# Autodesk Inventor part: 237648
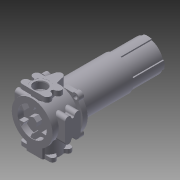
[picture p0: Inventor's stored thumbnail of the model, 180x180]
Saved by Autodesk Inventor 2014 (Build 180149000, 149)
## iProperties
Shininess: 20.0
Length Units: 11272
Angle Units: 11279
Time Units: 11290
Mass Units: 11286
Length Display Precision: 3
Angle Display Precision: 2
Company: Autodesk, Inc.
Created: 2002-06
Part Number: 237648
Material: Aluminum-6061
Description: FILTER
Document SubType Name: Modeling
Designer: Autodesk, Inc.
Density: 2.71 g/cm^3
Mass: 11418.8 g
Surface Area: 2406.98 cm^2
Volume: 4213.59 cm^3
Appearance: Metal-AL-6061(Flat)
Density: 0.0
Volumn: 0.0
Area: 0.0
PropertySet Name: Model Information
Control State: 0
Master: False
Checked Out: False
Last Check In By: JT
Last Check In Date: 2003-06-20
Title: FILTER
Author: Autodesk, Inc.
Comments: POSITIONAL ACCURACY OF ALL PORTS IS QUESTIONABLE.  CHECK FOR YOUR APPLICATION.
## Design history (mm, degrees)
sketch "Sketch1"
  geometry: C1 r 54.769 at (0, 0); 1 further point
  constraints: 1 centre point, 1 coincident
  dimensions: "d3" = 109.5375 diameter of C1
extrude "Extrusion2" new body sketch "Sketch1" distance "d4" = 273.685; taper "d5" = 0 deg
sketch "Sketch2"
  geometry: L1 (-49.187, 12.7)-(-60.596, 12.7); L2 (-12.7, 60.596)-(-12.7, 49.187); L3 (12.7, 60.596)-(12.7, 49.187); L4 (60.596, 12.7)-(49.187, 12.7); L5 (49.187, -12.7)-(60.596, -12.7); L6 (12.7, -49.187)-(12.7, -60.596); L7 (-12.7, -49.187)-(-12.7, -60.596); L8 (-60.596, -12.7)-(-49.187, -12.7); C1 r 54.769 at (0, 0) reference; A1 r 50.8 centre (0, 0) between (-12.7, 49.187) and (-49.187, 12.7); A2 r 50.8 centre (0, 0) between (49.187, 12.7) and (12.7, 49.187); A3 r 50.8 centre (0, 0) between (-49.187, -12.7) and (-12.7, -49.187); A4 r 50.8 centre (0, 0) between (12.7, -49.187) and (49.187, -12.7); 1 further point
  constraints: 16 end point, 8 parallel, 8 point on circle, 4 centre point, 4 collinear, 4 perpendicular, 3 concentric, 2 vertical, 1 coincident, 10 other
  dimensions: "d6" = 50.8 radius of A2; "d7" = 12.7 distance from line of point (0, 0) L3; "d8" = 25.4 distance between parallel lines of L2 L3; "d9" = 12.7 distance from line of point (0, 0) L4; "d10" = 25.4 distance between parallel lines of L5 L4
extrude "Extrusion3" cut sketch "Sketch2" distance "d11" = 101.6; taper "d12" = 0 deg
sketch "Sketch3"
  geometry: L1 (-43.017, 60.96)-(43.017, 60.96); L2 (43.017, -60.96)-(-43.017, -60.96); C1 r 61.912 at (0, 0); C2 r 6.731 at (-52.388, 52.388); C3 r 6.731 at (52.388, 52.388); C4 r 6.731 at (52.388, -52.388); C5 r 6.731 at (-52.388, -52.388); C6 r 54.769 at (0, 0) reference; A1 r 12.7 centre (-52.388, -52.388) between (-62.48, -44.678) and (-43.017, -60.96); A2 r 12.7 centre (52.388, -52.388) between (43.017, -60.96) and (62.348, -44.508); A3 r 12.7 centre (52.388, 52.388) between (62.348, 44.508) and (43.017, 60.96); A4 r 12.7 centre (-52.388, 52.388) between (-43.017, 60.96) and (-62.48, 44.678); A5 r 76.604 centre (-0.254, 0) between (-62.48, 44.678) and (-62.48, -44.678); A6 r 76.604 centre (0, 0) between (62.348, -44.508) and (62.348, 44.508)
  constraints: 12 point on circle, 11 centre point, 7 equal radius, 6 coincident, 4 end point, 4 vertical alignment, 2 horizontal alignment, 2 parallel, 1 horizontal
  dimensions: "d13" = 13.462 diameter of C2; "d18" = 25.4 diameter of A4; "d19" = 60.96 distance from line of C1.centre L1; "d23" = 0.254 distance of A5.centre A6.centre; "d83" = 123.825 diameter of C1; "d84" = 52.3875 horizontal distance of A6.centre C2.centre; "d85" = 104.775 distance of C3.centre C2.centre; "d87" = 52.3875 vertical distance of C2.centre A5.centre
extrude "Extrusion4" join sketch "Sketch3" distance "d24" = 15.875; taper "d25" = 0 deg
sketch "Sketch4"
  geometry: L1 (-44.678, 15.875)-(44.678, 15.875) reference; L2 (61.912, 15.875)-(61.912, 88.9); L3 (61.912, 88.9)-(63.5, 88.9); L4 (63.5, 88.9)-(63.5, 98.425); L5 (63.5, 98.425)-(66.675, 98.425); L6 (66.675, 98.425)-(66.675, 104.775); L7 (66.675, 104.775)-(47.625, 104.775); L8 (0, 0)-(0, 153.89); L9 (61.912, 15.875)-(0, 15.875); L10 (0, 85.725)-(0, 15.875); L11 (47.625, 104.775)-(47.625, 85.725); L12 (47.625, 85.725)-(0, 85.725)
  constraints: 22 end point, 5 parallel, 4 perpendicular, 2 point on line, 1 collinear, 1 midpoint
  dimensions: "d26" = 133.35 diameter of L6 L8; "d27" = 6.35 distance of L5.end L6.end; "d28" = 9.525 distance of L3.end L4.end; "d29" = 127 diameter of L4 L8; "d30" = 123.825 diameter of L2 L8; "d31" = 88.9 distance between parallel lines of L1 L7; "d32" = 95.25 diameter of L11 L8; "d33" = 19.05 distance of L7.end L11.end
revolve "Revolution1" sketch "Sketch4" stored, may be unused: angle "d34" = 90 deg
sketch "Sketch5"
  geometry: L1 (-7.84, 46.975)-(-1.439, 33.248); L2 (1.439, 33.248)-(7.84, 46.975); L3 (7.84, 46.975)-(-7.84, 46.975); L4 (-44.602, 16.698)-(-29.513, 15.378); L5 (-28.074, 17.87)-(-36.762, 30.277); L6 (-36.762, -30.277)-(-28.074, -17.87); L7 (-29.513, -15.378)-(-44.602, -16.698); L8 (7.84, -46.975)-(1.439, -33.248); L9 (-1.439, -33.248)-(-7.84, -46.975); L10 (44.602, -16.698)-(29.513, -15.378); L11 (28.074, -17.87)-(36.762, -30.277); L12 (36.762, 30.277)-(28.074, 17.87); L13 (29.513, 15.378)-(44.602, 16.698); L14 (-11.005, 9.509)-(2.733, 14.285); L15 (2.733, 14.285)-(13.737, 4.776); L16 (13.737, 4.776)-(11.005, -9.509); L17 (11.005, -9.509)-(-2.733, -14.285); L18 (-2.733, -14.285)-(-13.737, -4.776); L19 (-13.737, -4.776)-(-11.005, 9.509); A1 r 47.625 centre (0, 0) between (-7.84, 46.975) and (7.84, 46.975) reference; A2 r 1.587 centre (-29.375, 16.959) between (-29.513, 15.378) and (-28.074, 17.87); A3 r 1.587 centre (-29.375, -16.959) between (-28.074, -17.87) and (-29.513, -15.378); A4 r 1.588 centre (0, -33.919) between (1.439, -33.248) and (-1.439, -33.248); A5 r 1.587 centre (29.375, -16.959) between (29.513, -15.378) and (28.074, -17.87); A6 r 1.588 centre (29.375, 16.959) between (28.074, 17.87) and (29.513, 15.378); A7 r 1.588 centre (0, 33.919) between (-1.439, 33.248) and (1.439, 33.248); A8 r 47.625 centre (0, 0) between (-7.84, -46.975) and (7.84, -46.975); A9 r 47.625 centre (0, 0) between (36.762, -30.277) and (44.602, -16.698); A10 r 47.625 centre (0, 0) between (44.602, 16.698) and (36.762, 30.277); A11 r 47.625 centre (0, 0) between (7.84, 46.975) and (-7.84, 46.975); A12 r 47.625 centre (0, 0) between (-36.762, 30.277) and (-44.602, 16.698); A13 r 47.625 centre (0, 0) between (-44.602, -16.698) and (-36.762, -30.277); 8 further points
  constraints: 38 end point, 26 point on circle, 12 centre point, 12 point on line, 12 tangent, 4 equal radius, 2 coincident, 1 horizontal, 1 vertical alignment, 44 other
  dimensions: "d35" = 50 deg angle of L1 L2; "d36" = 30.1625 distance of A1.centre point (0, 30.162); "d39" = 360 deg dimension on A1.centre L1.start (derived); "d41" = 1.5875 radius of A2; "d42" = 1.5875 radius of A3
extrude "Extrusion5" join sketch "Sketch5" distance "d43" = 17.4625; taper "d44" = 0 deg
sketch "Sketch6"
  geometry: L1 (-29.369, 79.756)-(29.369, 79.756); L2 (29.369, 28.956)-(-29.369, 28.956); L3 (-29.369, 69.437)-(29.369, 39.275); L4 (0, 54.356)-(29.369, 69.437); A1 r 10.319 centre (29.369, 69.437) between (31.121, 59.268) and (29.369, 79.756); A2 r 4.985 centre (31.967, 54.356) between (31.121, 59.268) and (31.121, 49.444); A3 r 10.319 centre (29.369, 39.275) between (29.369, 28.956) and (31.121, 49.444); A4 r 10.319 centre (-29.369, 39.275) between (-31.121, 49.444) and (-29.369, 28.956); A5 r 4.985 centre (-31.967, 54.356) between (-31.121, 49.444) and (-31.121, 59.268); A6 r 10.319 centre (-29.369, 69.437) between (-29.369, 79.756) and (-31.121, 59.268); 1 further point
  constraints: 12 point on circle, 8 end point, 7 tangent, 6 centre point, 3 equal radius, 3 vertical alignment, 2 horizontal alignment, 1 horizontal, 1 midpoint, 1 parallel
  dimensions: "d45" = 30.1625 distance of A4.centre L3.start; "d46" = 58.7375 distance of L4.end L3.start; "d47" = 10.31875 radius of A6; "d48" = 54.356 distance of point (0, 0) L4.start
extrude "Extrusion6" join sketch "Sketch6" stored distance "d49" = 165.1; taper "d50" = 0 deg
workplane "Work Plane1"
sketch "Sketch8"
  geometry: L1 (35.076, 102.787)-(34.925, 102.787); L2 (34.925, 102.787)-(-34.925, 102.787); L3 (19.05, 43.263)-(12.331, 16.01); L4 (-12.331, 16.01)-(-19.05, 43.263); L5 (-34.925, 90.881)-(34.925, 55.169); L6 (0, 73.025)-(34.925, 90.881); L7 (-34.925, 43.263)-(-19.05, 43.263); L8 (19.05, 43.263)-(34.925, 43.263); A1 r 11.906 centre (-34.925, 90.881) between (-34.925, 102.787) and (-35.869, 79.012); A2 r 6.006 centre (-36.345, 73.025) between (-35.869, 67.038) and (-35.869, 79.012); A3 r 11.906 centre (-34.925, 55.169) between (-35.869, 67.038) and (-34.925, 43.263); A4 r 11.906 centre (34.925, 55.169) between (34.925, 43.263) and (33.981, 67.038); A5 r 6.006 centre (33.505, 73.025) between (33.981, 79.012) and (33.981, 67.038); A6 r 11.906 centre (34.925, 90.881) between (33.981, 79.012) and (34.925, 102.787); A7 r 12.7 centre (0, 19.05) between (-12.331, 16.01) and (12.331, 16.01); 1 further point
  constraints: 16 end point, 14 point on circle, 11 tangent, 7 centre point, 4 vertical alignment, 3 equal radius, 2 horizontal alignment, 2 parallel, 1 collinear, 1 horizontal, 1 midpoint
  dimensions: "d56" = 35.7124 distance of L5.end L6.end; "d57" = 69.85 distance of L5.start L6.end; "d58" = 19.05 horizontal distance of L3.start A7.centre; "d59" = 19.05 horizontal distance of L4.end A7.centre; "d60" = 12.7 radius of A7; "d61" = 73.025 distance of L6.start point (0, 0); "d62" = 11.90625 radius of A6; "d63" = 19.05 distance of point (0, 0) A7.centre
extrude "Extrusion8" join sketch "Sketch8" distance "d64" = 15.875; taper "d65" = 0 deg
sketch "Sketch9"
  geometry: L1 (-19.05, -43.263)-(-24.715, -67.168); L2 (19.05, -43.263)-(24.715, -67.168); L3 (19.05, -43.263)-(12.331, -16.01) reference; L4 (-12.331, -16.01)-(-19.05, -43.263) reference; L5 (-19.05, -43.263)-(-12.331, -16.01); L6 (12.331, -16.01)-(19.05, -43.263); A1 r 12.7 centre (0, -19.05) between (12.331, -16.01) and (-12.331, -16.01) reference; A2 r 25.4 centre (0, -73.025) between (-24.715, -67.168) and (24.715, -67.168); 1 further point
  constraints: 8 end point, 4 tangent, 2 collinear, 2 point on circle, 1 centre point, 1 vertical alignment
  dimensions: "d66" = 50.8 diameter of A2; "d67" = 73.025 distance of point (0, 0) A2.centre
extrude "Extrusion9" join sketch "Sketch9" stored distance "d68" = 15.875; taper "d69" = 0 deg
workplane "Work Plane2"
sketch "Sketch10"
  geometry: L1 (25.4, 97.401)-(-25.4, 97.401); L2 (-25.4, 97.401)-(-28.575, 92.075); L3 (-28.575, 92.075)-(-44.45, 92.075); L4 (-21.001, 11.214)-(21.001, 11.214); L5 (44.45, 92.075)-(28.575, 92.075); L6 (28.575, 92.075)-(25.4, 97.401); L7 (-44.45, 22.225)-(-28.575, 22.225); L8 (-28.575, 22.225)-(-21.001, 11.214); L9 (44.45, 22.225)-(28.575, 22.225); L10 (28.575, 22.225)-(21.001, 11.214); L11 (44.45, 82.55)-(-44.45, 31.75); L12 (-44.45, 82.55)-(0, 57.15); L13 (0, 97.401)-(0, 11.214); L14 (-66.675, 104.775)-(66.675, 104.775) reference; C1 r 19.05 at (0, 57.15); A1 r 9.525 centre (-44.45, 82.55) between (-44.45, 92.075) and (-49.344, 74.379); A2 r 20.082 centre (-59.663, 57.15) between (-49.344, 39.921) and (-49.344, 74.379); A3 r 9.525 centre (-44.45, 31.75) between (-49.344, 39.921) and (-44.45, 22.225); A4 r 9.525 centre (44.45, 31.75) between (44.45, 22.225) and (49.059, 40.086); A5 r 19.499 centre (58.494, 57.15) between (49.059, 74.214) and (49.059, 40.086); A6 r 9.525 centre (44.45, 82.55) between (49.059, 74.214) and (44.45, 92.075); 1 further point
  constraints: 26 end point, 12 point on circle, 8 tangent, 7 centre point, 5 vertical alignment, 4 parallel, 3 equal radius, 3 midpoint, 2 equal length, 2 horizontal, 2 horizontal alignment, 1 coincident, 1 point on line, 1 vertical
  dimensions: "d71" = 57.15 distance of point (0, 0) C1.centre; "d72" = 50.8 distance of A4.centre L11.start; "d73" = 88.9 distance of L12.start L11.start; "d78" = 38.1 diameter of C1; "d90" = 47.625 distance from line of C1.centre L14 (derived)
extrude "Extrusion10" join sketch "Sketch10" distance "d79" = 12.7; taper "d80" = 0 deg
sketch "Sketch11"
  geometry: L1 (-25.4, 97.401)-(25.4, 97.401) reference; L2 (-21.001, 11.214)-(-28.575, 22.225) reference; L3 (21.001, 11.214)-(-21.001, 11.214) reference; L4 (28.575, 22.225)-(21.001, 11.214) reference; L5 (25.4, 97.401)-(28.575, 92.075) reference; L6 (-28.575, 92.075)-(-25.4, 97.401); L7 (25.4, 97.401)-(-25.4, 97.401); L8 (28.575, 92.075)-(25.4, 97.401); L9 (28.575, 22.225)-(21.001, 11.214); L10 (21.001, 11.214)-(-21.001, 11.214); L11 (-21.001, 11.214)-(-28.575, 22.225); C1 r 19.05 at (0, 57.15) reference; A1 r 45.125 centre (0, 57.15) between (-28.575, 92.075) and (-28.575, 22.225); A2 r 45.125 centre (0, 57.15) between (28.575, 22.225) and (28.575, 92.075)
  constraints: 14 end point, 5 collinear, 4 point on circle, 2 centre point, 1 coincident
extrude "Extrusion11" join sketch "Sketch11" stored distance "d81" = 25.4; taper "d82" = 0 deg
workplane "Work Plane3"
sketch "Sketch12"
  geometry: L1 (12.331, 89.662)-(-12.331, 89.662) reference; L2 (-12.331, 89.662)-(-19.05, 89.662) reference; L3 (-19.05, 89.662)-(-34.925, 89.662) reference; L4 (19.05, 89.662)-(12.331, 89.662) reference; L5 (34.925, 89.662)-(19.05, 89.662) reference; L6 (0, 89.662)-(0, 27.389); L7 (-15.875, 35.979)-(-15.875, 61.379); L8 (-15.875, 61.379)-(-20.637, 66.142); L9 (-20.637, 66.142)-(-20.638, 85.801); L10 (-20.638, 85.801)-(-21.536, 89.154); L11 (-21.536, 89.154)-(-28.829, 89.154); L12 (-28.829, 89.154)-(-28.829, 89.662); L13 (-15.875, 35.979)-(0, 27.389)
  constraints: 16 end point, 3 parallel, 2 perpendicular, 1 midpoint, 1 point on line
  dimensions: "d92" = 57.658 diameter of L12 L6; "d93" = 0.508 distance between parallel lines of L3 L11; "d94" = 15 deg angle of L10 L9; "d95" = 41.275 diameter of L9 L6; "d96" = 3.3528 vertical distance of L9.end L10.end; "d97" = 23.0124 distance from line of L8.end L11; "d98" = 45 deg angle of L7 L8; "d99" = 25.4 distance of L7.start L7.end; "d100" = 31.75 diameter of L7 L6
revolve "Revolution2" sketch "Sketch12" stored, may be unused: angle "d101" = 90 deg
body "Solid1"
other parameters: "d55" = 89.662, "d70" = -96.8375, "d91" = -26.9875
